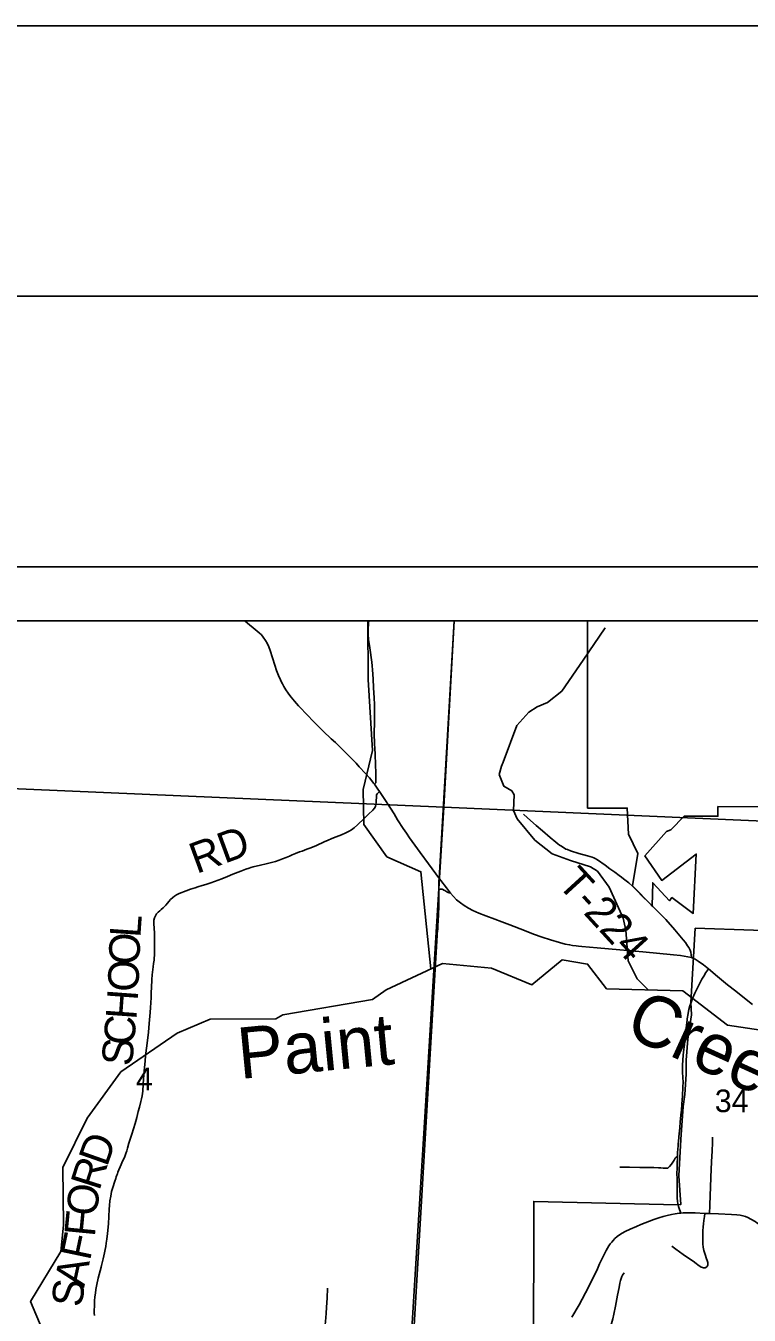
# Model space of a CAD drawing. Extents: x 21.4 to 65.3, y 4 to 26.
# Drawn here: x 25.81 to 27.146, y 23.571 to 25.954 of the extents above; entities that cross this region are included whole.
import ezdxf

# ---------------------------------------------------------------- set-up
doc = ezdxf.new("R2010")
doc.units = 0
for name, color, linetype in [('Default', 7, 'Continuous'), ('GM_X_City_Street', 7, 'Continuous'), ('GM_X_County_Road', 7, 'Continuous'), ('GM_X_Minor_River', 7, 'Continuous'), ('GM_X_Minor_River_Text', 7, 'Continuous'), ('GM_X_Section', 7, 'Continuous'), ('GM_X_Section_Text', 7, 'Continuous'), ('GM_X_State_Route', 7, 'Continuous'), ('GM_X_Township_Road', 7, 'Continuous'), ('GM_X_Township_Road_Text', 7, 'Continuous'), ('SH_Border', 7, 'Continuous'), ('SH_Cut_Line', 7, 'Continuous'), ('SH_Data', 7, 'Continuous')]:
    doc.layers.add(name, color=color, linetype=linetype)

msp = doc.modelspace()

# ---------------------------------------------------------------- linework, layer by layer
at = {"layer": 'Default'}
for points in [[(26.3906, 21.3613), (26.4573, 22.45), (26.4915, 22.9722), (26.4968, 23.0532), (26.5076, 23.2181), (26.5201, 23.4302), (26.5253, 23.5099), (26.571, 24.2838), (26.5714, 24.2916), (26.5716, 24.3007), (26.5721, 24.3116), (26.5728, 24.3278), (26.5729, 24.3421), (26.5729, 24.3464), (26.5731, 24.3575), (26.5731, 24.358), (26.5731, 24.3616), (26.5731, 24.3659), (26.5732, 24.3694), (26.5734, 24.3737), (26.5741, 24.3781), (26.6018, 24.8542), (23.5473, 24.8542), (23.5473, 20.5568)], [(29.9103, 24.8542), (26.6018, 24.8542), (26.5741, 24.3781), (26.5734, 24.3737), (26.5732, 24.3694), (26.5731, 24.3659), (26.5731, 24.3616), (26.5731, 24.358), (26.5731, 24.3575), (26.5729, 24.3464), (26.5729, 24.3421), (26.5728, 24.3278), (26.5721, 24.3116), (26.5716, 24.3007), (26.5714, 24.2916), (26.571, 24.2838), (26.5253, 23.5099), (26.5201, 23.4302), (26.5076, 23.2181), (26.4968, 23.0532), (26.4915, 22.9722), (26.4573, 22.45), (26.3906, 21.3613)], [(27.4006, 24.8542), (26.8479, 24.8542), (26.8479, 24.5082), (26.921, 24.5082), (26.9236, 24.4598), (26.9408, 24.4241), (26.9307, 24.3644), (26.9672, 24.3277), (26.9683, 24.3703), (26.9991, 24.337), (27.0036, 24.3427), (27.0431, 24.3137), (27.0485, 24.4232), (26.9849, 24.3746), (26.9539, 24.4197), (26.9934, 24.4651), (27.0014, 24.468), (27.0264, 24.493), (27.0885, 24.493), (27.0885, 24.511), (27.2758, 24.51)], [(27.2617, 24.2788), (27.0467, 24.2862), (27.0387, 24.1492), (27.0395, 24.1264), (27.0333, 24.0811), (27.0301, 24.0425), (27.0297, 24.0164), (27.0275, 23.9786), (27.0243, 23.9566), (27.0198, 23.8955), (27.0162, 23.8283), (27.0198, 23.7753), (27.0146, 23.7751), (26.7486, 23.7813), (26.7481, 23.4797)]]:
    msp.add_lwpolyline(points, dxfattribs=at)
for points in [[(26.6018, 24.8542), (25.5568, 24.8542), (25.5389, 24.555), (26.5825, 24.5101)], [(27.636, 24.8542), (26.6018, 24.8542), (26.5825, 24.5101), (27.6091, 24.4648)]]:
    msp.add_lwpolyline(points, close=True, dxfattribs=at)
at = {"layer": 'GM_X_City_Street'}
for points in [[(27.0729, 23.7589), (27.0735, 23.7735), (27.0741, 23.7929), (27.0747, 23.8071), (27.0757, 23.8263), (27.0767, 23.8542), (27.0777, 23.875), (27.0783, 23.8896), (27.0785, 23.9)], [(27.0033, 23.6988), (27.0108, 23.6932), (27.0243, 23.6834), (27.0324, 23.6778), (27.0426, 23.6707), (27.0485, 23.6662), (27.0516, 23.6641), (27.0577, 23.66), (27.06, 23.659), (27.0618, 23.6585), (27.0636, 23.6584), (27.0649, 23.6586), (27.0661, 23.6591), (27.0671, 23.6596), (27.068, 23.6603), (27.0689, 23.6615), (27.0694, 23.6624), (27.0698, 23.6634), (27.0701, 23.6648), (27.0702, 23.6659), (27.0702, 23.6668), (27.0699, 23.6685), (27.0688, 23.6719), (27.0674, 23.6753), (27.0649, 23.6829), (27.0628, 23.6907), (27.0616, 23.6968), (27.0609, 23.7029), (27.0605, 23.7102), (27.0606, 23.7176), (27.0608, 23.7269), (27.0613, 23.7341), (27.0618, 23.7399), (27.0626, 23.746), (27.0636, 23.7532), (27.0644, 23.7592)], [(26.877, 23.5119), (26.8781, 23.5127), (26.8787, 23.5134), (26.8794, 23.5143), (26.88, 23.5158), (26.8808, 23.5179), (26.8823, 23.5225), (26.8873, 23.5397), (26.8906, 23.5512), (26.8943, 23.5645), (26.8963, 23.5731), (26.8994, 23.5875), (26.9034, 23.6082), (26.9059, 23.6222), (26.9076, 23.63), (26.9088, 23.6349), (26.9105, 23.6409), (26.9111, 23.6426), (26.9122, 23.6448), (26.9152, 23.6491)]]:
    msp.add_lwpolyline(points, dxfattribs=at)
at = {"layer": 'GM_X_County_Road'}
msp.add_lwpolyline([(26.4543, 24.5523), (26.4558, 24.5536), (26.4567, 24.5551), (26.457, 24.557), (26.457, 24.5609), (26.4569, 24.5733), (26.4565, 24.5879), (26.4555, 24.6078), (26.4549, 24.6184), (26.4545, 24.6272), (26.454, 24.6459), (26.4541, 24.6679), (26.4542, 24.6843), (26.4541, 24.6996), (26.4537, 24.712), (26.4527, 24.7308), (26.4517, 24.747), (26.4504, 24.7637), (26.4499, 24.7713), (26.4492, 24.7779), (26.4455, 24.8043), (26.4436, 24.8198), (26.4428, 24.8296), (26.4426, 24.8363), (26.4427, 24.8415), (26.443, 24.8462), (26.4435, 24.8504), (26.444, 24.8536), (26.4442, 24.8542)], dxfattribs=at)
at = {"layer": 'GM_X_Minor_River'}
for points in [[(26.5585, 24.2109), (26.54, 24.3905), (26.4774, 24.4181), (26.4345, 24.4776), (26.4336, 24.5425), (26.4505, 24.6148), (26.4427, 24.7456), (26.4422, 24.8542)], [(26.9596, 24.1721), (26.9394, 24.1927), (26.9228, 24.2257), (26.9186, 24.2824), (26.9137, 24.3048), (26.8879, 24.3622), (26.866, 24.3918), (26.8535, 24.3994), (26.8163, 24.4115), (26.7822, 24.4236), (26.7507, 24.4491), (26.7178, 24.4882), (26.711, 24.5038), (26.7121, 24.5327), (26.7079, 24.5399), (26.6935, 24.5486), (26.6844, 24.5703), (26.6886, 24.5859), (26.6917, 24.5931), (26.7171, 24.6608), (26.7391, 24.6855), (26.7546, 24.6954), (26.7736, 24.7034), (26.8001, 24.7244), (26.8396, 24.7814), (26.8805, 24.8415)], [(27.1676, 24.0975), (27.1064, 24.1072), (27.0239, 24.1706), (26.883, 24.1739), (26.8479, 24.2199), (26.8007, 24.2278), (26.7448, 24.1817), (26.6703, 24.2122), (26.5799, 24.2209), (26.4761, 24.1725), (26.4509, 24.1545), (26.2854, 24.1264), (26.2722, 24.1187), (26.1507, 24.1184), (26.0899, 24.092), (25.9861, 24.0209), (25.9235, 23.9353), (25.8787, 23.8439), (25.8801, 23.7372), (25.8751, 23.6886), (25.8194, 23.5963), (25.8409, 23.5452)]]:
    msp.add_lwpolyline(points, dxfattribs=at)
at = {"layer": 'GM_X_Section'}
for points in [[(26.5825, 24.5101), (26.5198, 23.4854), (25.4788, 23.5287), (25.4893, 23.7114), (25.5145, 24.1345), (25.5389, 24.555)], [(26.5825, 24.5101), (27.6091, 24.4648), (27.5486, 23.5443), (27.5415, 23.5386), (27.5313, 23.5298), (27.5214, 23.5207), (27.5097, 23.5112), (27.4908, 23.4937), (27.4682, 23.4724), (27.4508, 23.456), (27.444, 23.4496), (27.4376, 23.4427), (26.5198, 23.4854)]]:
    msp.add_lwpolyline(points, close=True, dxfattribs=at)
at = {"layer": 'GM_X_State_Route'}
for points in [[(26.2148, 24.8542), (26.22, 24.8499), (26.2339, 24.8385), (26.2378, 24.8355), (26.2415, 24.8323), (26.2455, 24.8285), (26.249, 24.8243), (26.253, 24.8182), (26.256, 24.8128), (26.2592, 24.8061), (26.2617, 24.7992), (26.2658, 24.7862), (26.2705, 24.7721), (26.2737, 24.7625), (26.2773, 24.7532), (26.2808, 24.7453), (26.2828, 24.7407), (26.2843, 24.738), (26.287, 24.7331), (26.2904, 24.7271), (26.2947, 24.7209), (26.3, 24.714), (26.3006, 24.7132)], [(26.3006, 24.7132), (26.3068, 24.7058), (26.3142, 24.6974), (26.3188, 24.6924), (26.3269, 24.6838), (26.3447, 24.6655), (26.3597, 24.6506), (26.3745, 24.6365), (26.3822, 24.6293), (26.3889, 24.6228), (26.3977, 24.6141), (26.4047, 24.6071), (26.41, 24.6019), (26.413, 24.5988), (26.4203, 24.5911), (26.4261, 24.5847), (26.438, 24.572), (26.445, 24.5641), (26.4493, 24.5589), (26.4527, 24.5545), (26.4543, 24.5523), (26.4607, 24.5434), (26.4638, 24.5388), (26.4725, 24.526), (26.4762, 24.5203), (26.4793, 24.5157), (26.4838, 24.5083), (26.4904, 24.4977), (26.4971, 24.4866), (26.5007, 24.4808), (26.5038, 24.4761), (26.5075, 24.4703), (26.5134, 24.4616), (26.519, 24.4534), (26.5385, 24.4261), (26.5539, 24.405), (26.5744, 24.3776)], [(26.5744, 24.3776), (26.577, 24.3741), (26.5872, 24.3608), (26.5949, 24.3508), (26.6002, 24.3448), (26.6061, 24.3389), (26.6131, 24.333), (26.6198, 24.3279), (26.628, 24.3232), (26.6358, 24.3191), (26.6472, 24.314), (26.6599, 24.309), (26.6765, 24.3028), (26.6898, 24.2981), (26.7045, 24.2924), (26.7316, 24.2818), (26.7482, 24.2754), (26.7639, 24.2698), (26.7794, 24.2646), (26.7962, 24.2597), (26.8065, 24.257), (26.8145, 24.2555), (26.8203, 24.2543), (26.8269, 24.2535), (26.831, 24.2531), (26.8373, 24.2524), (26.8513, 24.2511), (26.8653, 24.2499), (26.9077, 24.2464), (26.9497, 24.2427), (27.0065, 24.2371), (27.0194, 24.2357), (27.0333, 24.2333), (27.0399, 24.2319)], [(27.0399, 24.2319), (27.0436, 24.2304), (27.0467, 24.2287), (27.0518, 24.2254), (27.0618, 24.2184), (27.0709, 24.2109), (27.0876, 24.197), (27.1065, 24.1818), (27.1215, 24.1698), (27.1377, 24.1571), (27.1526, 24.1451)], [(26.8188, 23.5673), (26.8322, 23.5904), (26.8379, 23.6006), (26.8503, 23.6242), (26.8572, 23.6381), (26.8622, 23.6488), (26.8659, 23.6567), (26.87, 23.6657), (26.8764, 23.6792), (26.8797, 23.6859), (26.8821, 23.6903), (26.8847, 23.695), (26.8872, 23.6989), (26.8897, 23.7028), (26.8924, 23.7062), (26.8952, 23.7093), (26.8984, 23.7126), (26.9027, 23.7164), (26.907, 23.7196), (26.9119, 23.7226), (26.9174, 23.7257), (26.9264, 23.73), (26.9379, 23.7349), (26.9464, 23.7386), (26.962, 23.7449), (26.9702, 23.748), (26.9797, 23.7509), (26.9877, 23.7531), (26.9947, 23.7551), (27.0026, 23.757), (27.0099, 23.7585), (27.0167, 23.7594), (27.0199, 23.7597)], [(27.0199, 23.7597), (27.0242, 23.76), (27.0317, 23.7602), (27.0466, 23.7599), (27.0644, 23.7592), (27.0729, 23.7589), (27.0894, 23.7584), (27.1136, 23.7573), (27.1235, 23.7566), (27.1297, 23.7557), (27.1346, 23.7547), (27.1394, 23.7531), (27.1441, 23.7513), (27.1492, 23.7487), (27.1572, 23.7439), (27.1604, 23.7419), (27.1787, 23.7302), (27.1864, 23.725), (27.1899, 23.7225), (27.1927, 23.72), (27.1955, 23.7165)]]:
    msp.add_lwpolyline(points, dxfattribs=at)
at = {"layer": 'GM_X_Township_Road'}
for points in [[(26.2262, 24.3983), (26.2303, 24.3994), (26.2436, 24.4027), (26.2544, 24.4052), (26.2641, 24.4076), (26.2718, 24.4098), (26.2783, 24.4121), (26.2846, 24.4145), (26.291, 24.417), (26.2972, 24.4195), (26.3024, 24.4216), (26.3087, 24.4242), (26.3161, 24.4272), (26.3208, 24.4288), (26.3254, 24.4306), (26.3295, 24.4321), (26.3365, 24.4346), (26.3474, 24.439), (26.3614, 24.4456), (26.3687, 24.449), (26.3744, 24.4515), (26.3784, 24.4531), (26.3935, 24.4588), (26.4015, 24.4622), (26.4075, 24.4654), (26.4117, 24.4681), (26.4166, 24.4718), (26.4227, 24.4771), (26.4353, 24.4891), (26.4434, 24.4969), (26.4516, 24.5045), (26.4544, 24.5078), (26.4557, 24.5099), (26.4564, 24.5116), (26.4569, 24.514), (26.4574, 24.519), (26.4576, 24.5233), (26.4578, 24.5264), (26.458, 24.5313), (26.4582, 24.533), (26.459, 24.5344), (26.4614, 24.5366), (26.4638, 24.5388)], [(26.7294, 24.4969), (26.7367, 24.4903), (26.7528, 24.4762), (26.7649, 24.466), (26.7788, 24.454), (26.7895, 24.4454), (26.7932, 24.4422), (26.7963, 24.44), (26.7995, 24.4377), (26.8024, 24.4358), (26.8051, 24.434), (26.808, 24.4325), (26.8107, 24.4314), (26.8165, 24.4295), (26.8318, 24.4246), (26.8479, 24.4199), (26.8566, 24.4174), (26.8593, 24.4164), (26.8617, 24.4151), (26.8664, 24.4123), (26.8801, 24.4026), (26.8891, 24.3961), (26.8981, 24.3896), (26.906, 24.3838), (26.9107, 24.3803), (26.9114, 24.3798)], [(25.9494, 23.66), (25.9502, 23.6627), (25.9533, 23.6753), (25.9557, 23.6861), (25.9569, 23.6925), (25.958, 23.698), (25.9591, 23.7043), (25.9602, 23.7114), (25.9611, 23.7218), (25.9629, 23.7401), (25.9639, 23.7535), (25.9646, 23.7669), (25.9651, 23.7737), (25.9659, 23.7823), (25.9672, 23.7909), (25.9689, 23.7994), (25.971, 23.8072), (25.9746, 23.8184), (25.9765, 23.8236), (25.9775, 23.8265), (25.9788, 23.83), (25.9796, 23.8324), (25.9807, 23.8353), (25.9825, 23.8399), (25.9846, 23.8451), (25.9899, 23.8567), (25.9925, 23.8626), (25.9953, 23.8699), (25.9968, 23.8746), (25.9981, 23.8797), (26.001, 23.8892), (26.0027, 23.8945), (26.0062, 23.9057), (26.0092, 23.9152), (26.0123, 23.9253), (26.0155, 23.9366), (26.0182, 23.9474), (26.0203, 23.9552), (26.0231, 23.9658), (26.0243, 23.9711), (26.0252, 23.9766), (26.0263, 23.9851), (26.0273, 23.998), (26.0284, 24.0156), (26.0296, 24.0287), (26.0306, 24.0406), (26.0317, 24.051), (26.0342, 24.0686), (26.0368, 24.0938), (26.0383, 24.1098), (26.04, 24.1307), (26.0407, 24.1399), (26.0412, 24.1485), (26.0418, 24.1584), (26.0419, 24.1615), (26.0421, 24.1659), (26.0422, 24.1677), (26.0425, 24.1758), (26.0431, 24.1913), (26.0437, 24.2), (26.0455, 24.2148), (26.0464, 24.2209), (26.0472, 24.2271), (26.0476, 24.232), (26.0478, 24.2351), (26.0479, 24.2382), (26.0481, 24.2426), (26.0482, 24.2481), (26.0484, 24.258), (26.0484, 24.269), (26.0481, 24.277), (26.0473, 24.2862), (26.0467, 24.2942), (26.0467, 24.2985), (26.0469, 24.301), (26.048, 24.3052), (26.0497, 24.3091), (26.0521, 24.3127), (26.055, 24.3159), (26.0577, 24.3184), (26.0605, 24.3209), (26.0642, 24.3241), (26.0691, 24.3288), (26.0724, 24.3325), (26.0747, 24.3354), (26.0779, 24.3391), (26.0818, 24.343), (26.0852, 24.3457), (26.0889, 24.3479), (26.0939, 24.3502), (26.1065, 24.3552), (26.1144, 24.3583), (26.1232, 24.361), (26.1284, 24.3627), (26.1361, 24.3651), (26.1426, 24.3671), (26.1519, 24.3702), (26.1722, 24.3777), (26.1832, 24.382), (26.1929, 24.3859), (26.2073, 24.3918), (26.2166, 24.3953), (26.2231, 24.3974), (26.2262, 24.3983)], [(26.5712, 24.2833), (26.5716, 24.2911), (26.5718, 24.3002), (26.5723, 24.3111), (26.573, 24.3273), (26.5731, 24.3416), (26.5731, 24.3459), (26.5733, 24.357), (26.5733, 24.3611), (26.5733, 24.3654), (26.5734, 24.3689), (26.5736, 24.3732), (26.5744, 24.3776)], [(26.5733, 24.357), (26.5765, 24.3581), (26.5773, 24.3583), (26.5787, 24.3583), (26.5795, 24.3582), (26.5805, 24.3579), (26.5816, 24.3574), (26.5827, 24.3568), (26.5843, 24.3558), (26.5863, 24.3546), (26.5881, 24.3535), (26.5903, 24.3523), (26.5925, 24.3514), (26.5949, 24.3508)], [(26.9114, 24.3798), (26.9169, 24.3758), (26.924, 24.3698), (26.9309, 24.3639), (26.9316, 24.3632)], [(26.9316, 24.3632), (26.9408, 24.3538), (26.9483, 24.346), (26.9622, 24.3323), (26.9674, 24.3272), (26.9681, 24.3265)], [(26.9681, 24.3265), (26.9809, 24.3141), (26.9921, 24.3025), (27.0091, 24.2833), (27.0245, 24.2648), (27.0284, 24.2596), (27.0326, 24.2538), (27.0347, 24.2504), (27.0373, 24.2456), (27.038, 24.2438), (27.0384, 24.2417), (27.0399, 24.2319)], [(27.0389, 24.1486), (27.0416, 24.1561), (27.0462, 24.1662), (27.0493, 24.1725), (27.059, 24.192), (27.0623, 24.1977), (27.0663, 24.2042), (27.0697, 24.2092), (27.0709, 24.2109)], [(27.032, 24.1189), (27.0323, 24.1217), (27.0328, 24.1254), (27.0349, 24.1358), (27.0369, 24.1428), (27.0389, 24.1486)], [(27.0299, 24.0994), (27.0301, 24.1014), (27.0311, 24.1119), (27.0316, 24.1162), (27.032, 24.1189)], [(27.0211, 23.9494), (27.0219, 23.9612), (27.023, 23.9766), (27.024, 23.9925), (27.0241, 24.002), (27.0238, 24.0095), (27.0234, 24.0207), (27.0233, 24.0321), (27.0239, 24.0438), (27.0251, 24.0576), (27.0268, 24.0711), (27.0288, 24.0873), (27.0299, 24.0994)], [(27.0153, 23.8892), (27.0155, 23.8912), (27.0162, 23.9006), (27.018, 23.9173), (27.019, 23.9283), (27.0209, 23.9465), (27.0211, 23.9494)], [(27.0149, 23.7746), (27.0143, 23.7776), (27.0138, 23.7808), (27.0135, 23.7876), (27.0135, 23.8001), (27.0136, 23.8149), (27.0133, 23.8217), (27.0129, 23.834), (27.0131, 23.8414), (27.0134, 23.8489), (27.014, 23.864), (27.0142, 23.8715), (27.0149, 23.8841), (27.0153, 23.8892)], [(26.9076, 23.8448), (26.9254, 23.8444), (26.9446, 23.8441), (26.9618, 23.8439), (26.9703, 23.8437), (26.9787, 23.8434), (26.9833, 23.8431), (26.9877, 23.8428), (26.9911, 23.8424), (26.9935, 23.8424), (26.9948, 23.8426), (26.9958, 23.8429), (26.9968, 23.8434), (26.9993, 23.8456), (27.0027, 23.8501), (27.0075, 23.8575), (27.0098, 23.8611), (27.0107, 23.8624), (27.0115, 23.8632), (27.0126, 23.8639), (27.014, 23.864)], [(27.0199, 23.7597), (27.0187, 23.763), (27.0174, 23.7664), (27.0157, 23.7717), (27.0149, 23.7746)], [(25.9371, 23.5706), (25.9368, 23.5745), (25.9368, 23.5784), (25.9371, 23.5892), (25.9375, 23.5977), (25.9381, 23.6047), (25.9389, 23.6115), (25.9399, 23.6182), (25.9417, 23.6279), (25.9441, 23.6395), (25.9457, 23.6461), (25.9494, 23.66)], [(26.3627, 23.502), (26.3608, 23.5108), (26.3604, 23.5136), (26.3601, 23.5165), (26.3601, 23.5192), (26.3602, 23.5219), (26.3609, 23.5303), (26.3629, 23.5471), (26.364, 23.5595), (26.365, 23.5743), (26.3658, 23.586), (26.3667, 23.6027), (26.3677, 23.6212)]]:
    msp.add_lwpolyline(points, dxfattribs=at)
at = {"layer": 'SH_Border'}
msp.add_lwpolyline([(22.9473, 25.4542), (54.9473, 25.4542), (54.9473, 4.4542), (22.9473, 4.4542)], close=True, dxfattribs=at)
at = {"layer": 'SH_Cut_Line'}
msp.add_lwpolyline([(21.4473, 3.9542), (55.4473, 3.9542), (55.4473, 25.9542), (21.4473, 25.9542)], close=True, dxfattribs=at)
msp.add_lwpolyline([(29.9103, 24.8542), (23.5473, 24.8542)], dxfattribs=at)
at = {"layer": 'SH_Data'}
for p, q in [((23.4473, 24.9542), (30.4473, 24.9542)), ((23.5473, 24.8542), (30.3473, 24.8542))]:
    msp.add_line(p, q, dxfattribs=at)

# ---------------------------------------------------------------- texts
at = {"layer": 'GM_X_Minor_River_Text'}
for s, height, rotation, p in [('Creek', 0.09469, 335.5162, (26.9131, 24.0897)), ('Paint', 0.0947, 5.5114, (26.206, 24.0074))]:
    msp.add_text(s, height=height, rotation=rotation, dxfattribs=at).set_placement(p)
at = {"layer": 'GM_X_Section_Text'}
for s, height, p in [('4', 0.0419, (26.014, 23.9865)), ('34', 0.04186, (27.0828, 23.9462))]:
    msp.add_text(s, height=height, rotation=0, dxfattribs=at).set_placement(p)
at = {"layer": 'GM_X_Township_Road_Text'}
for s, height, rotation, p in [('RD', 0.05682, 20.1431, (26.1258, 24.3863)), ('T-224', 0.05682, 312.4626, (26.7903, 24.3671)), ('L', 0.0568, 86.0542, (26.0219, 24.2677)), ('O', 0.0568, 88.0202, (26.0202, 24.2182)), ('O', 0.0568, 87.6881, (26.0182, 24.1679)), ('H', 0.0568, 85.8751, (26.0145, 24.1161)), ('C', 0.0568, 84.6231, (26.01, 24.0682)), ('S', 0.0568, 84.5561, (26.0064, 24.03)), ('D', 0.0568, 70.5743, (25.9602, 23.8435)), ('R', 0.0568, 72.35, (25.9462, 23.7995)), ('O', 0.0568, 83.9197, (25.9415, 23.7527)), ('F', 0.0568, 84.4202, (25.9378, 23.7147)), ('F', 0.0568, 78.1009, (25.9289, 23.6704)), ('A', 0.0568, 77.6506, (25.9181, 23.6211)), ('S', 0.0568, 84.2795, (25.9145, 23.5847))]:
    msp.add_text(s, height=height, rotation=rotation, dxfattribs=at).set_placement(p)

doc.saveas('drawing.dxf')
